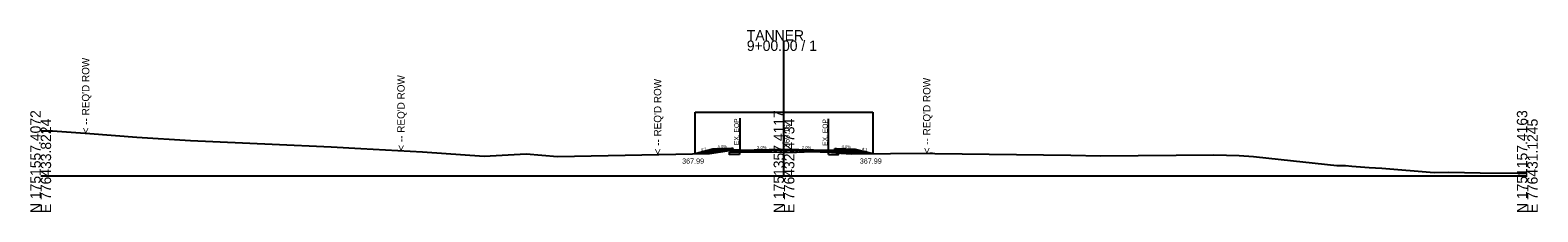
# Model space of a CAD drawing. Extents: x 774192 to 776597, y 1750236 to 1752784.
# Drawn here: x 774680.5 to 775086.2, y 1751748.9 to 1751797.8 of the extents above; entities that cross this region are included whole.
import ezdxf

# ---------------------------------------------------------------- set-up
doc = ezdxf.new("R2010")
doc.units = 0
for name, color, linetype in [('ControlPoints', 7, 'Continuous'), ('Default', 7, 'Continuous'), ('Observations', 7, 'Continuous'), ('Setups', 7, 'Continuous'), ('SHEET_BORDER_TX', 7, 'Continuous'), ('SHEET_DATE_DGN_TX', 7, 'Continuous'), ('SHEET_LOGO', 7, 'Continuous'), ('SHEET_PLOTTING_SHAPE', 7, 'Continuous'), ('SHEET_PRELIM', 7, 'Continuous'), ('SHEET_PROJ_NUMBER', 7, 'Continuous'), ('SHEET_TITLE_BLOCK_TX', 7, 'Continuous'), ('SHEET_WORK_NUMBER', 7, 'Continuous'), ('TS_BACKBONE', 7, 'Continuous'), ('TS_DIMENSIONS', 7, 'Continuous')]:
    doc.layers.add(name, color=color, linetype=linetype)

msp = doc.modelspace()

# ---------------------------------------------------------------- linework, layer by layer
at = {"layer": 'ControlPoints'}
msp.add_lwpolyline([(774683.33, 1751770.73), (774686.53, 1751770.71), (774696.56, 1751769.97), (774709.16, 1751768.98), (774723.68, 1751768.1), (774745.63, 1751767.12), (774761.49, 1751766.44), (774769.51, 1751765.91), (774786.05, 1751765.06), (774802.69, 1751763.89), (774813.95, 1751764.55), (774822.43, 1751763.79), (774863.28, 1751764.64), (774869.17, 1751765.48), (774869.52, 1751765.18), (774869.9, 1751765.28), (774871.42, 1751765.09), (774883.33, 1751764.99), (774886.74, 1751765), (774890.92, 1751765.1), (774895.22, 1751764.93), (774897.31, 1751764.76), (774901.44, 1751764.53), (774922.53, 1751764.66), (774923.32, 1751764.65), (774923.93, 1751764.64), (774960.53, 1751764.12), (774968.46, 1751764.01), (774998.95, 1751764.23), (775005.77, 1751764.07), (775009.7, 1751763.79), (775013.78, 1751763.39), (775032.11, 1751761.37), (775034.43, 1751761.33), (775036.09, 1751761.17), (775040.8, 1751760.86), (775044.2, 1751760.64), (775058.32, 1751759.48), (775062.18, 1751759.57), (775070.68, 1751759.42), (775080.8, 1751759.34), (775083.33, 1751759.3)], dxfattribs=at)
at = {"layer": 'Default'}
for p, q in [((774871.34, 1751765.33), (774883.34, 1751765.57)), ((774883.33, 1751765.57), (774895.33, 1751765.33))]:
    msp.add_line(p, q, dxfattribs=at)
at = {"layer": 'Setups'}
for p, q in [((774883.33, 1751758.57), (774883.33, 1751795.04)), ((774683.33, 1751758.57), (774883.33, 1751758.57)), ((774883.33, 1751758.57), (775083.33, 1751758.57))]:
    msp.add_line(p, q, dxfattribs=at)
at = {"layer": 'SHEET_BORDER_TX'}
for p, q in [((774868.67, 1751764.27), (774868.67, 1751764.94)), ((774871.35, 1751764.33), (774868.67, 1751764.27)), ((774895.32, 1751764.33), (774898, 1751764.27)), ((774898, 1751764.27), (774898, 1751764.94))]:
    msp.add_line(p, q, dxfattribs=at)
for points in [[(774868.67, 1751764.94), (774871.33, 1751764.99), (774871.35, 1751764.33)], [(774895.32, 1751764.33), (774895.33, 1751764.99), (774898, 1751764.94)]]:
    msp.add_lwpolyline(points, dxfattribs=at)
at = {"layer": 'SHEET_LOGO'}
for p, q in [((774871.42, 1751774.09), (774871.42, 1751765.09)), ((774895.22, 1751773.93), (774895.22, 1751764.93))]:
    msp.add_line(p, q, dxfattribs=at)
at = {"layer": 'SHEET_PLOTTING_SHAPE'}
for p, q in [((774869.17, 1751764.95), (774869.17, 1751765.95)), ((774871.33, 1751765.49), (774871.33, 1751764.99)), ((774895.33, 1751765.49), (774895.33, 1751764.99)), ((774897.5, 1751764.95), (774897.5, 1751765.95)), ((774871.33, 1751764.99), (774869.17, 1751764.95)), ((774895.33, 1751764.99), (774897.5, 1751764.95))]:
    msp.add_line(p, q, dxfattribs=at)
at = {"layer": 'SHEET_PROJ_NUMBER'}
for p, q in [((774859.42, 1751764.56), (774859.42, 1751775.73)), ((774859.42, 1751775.73), (774907.23, 1751775.73)), ((774907.23, 1751775.73), (774907.23, 1751764.57))]:
    msp.add_line(p, q, dxfattribs=at)
at = {"layer": 'SHEET_TITLE_BLOCK_TX'}
for p, q in [((774864.17, 1751765.75), (774859.42, 1751764.56)), ((774869.17, 1751765.95), (774864.17, 1751765.75)), ((774869.67, 1751765.96), (774869.17, 1751765.95)), ((774869.67, 1751765.46), (774869.67, 1751765.96)), ((774871.33, 1751765.49), (774869.67, 1751765.46)), ((774871.33, 1751765.49), (774883.33, 1751765.73)), ((774883.33, 1751765.73), (774895.33, 1751765.49)), ((774895.33, 1751765.49), (774897, 1751765.46)), ((774897, 1751765.46), (774897, 1751765.96)), ((774897, 1751765.96), (774897.5, 1751765.95)), ((774897.5, 1751765.95), (774902.5, 1751765.75)), ((774902.5, 1751765.75), (774907.23, 1751764.57))]:
    msp.add_line(p, q, dxfattribs=at)
at = {"layer": 'SHEET_WORK_NUMBER'}
msp.add_line((774895.33, 1751764.99), (774895.33, 1751764.92), dxfattribs=at)
for points in [[(774871.33, 1751765.11), (774871.42, 1751765.09), (774874.94, 1751765.06)], [(774874.94, 1751765.06), (774883.33, 1751764.99), (774886.74, 1751765), (774890.92, 1751765.1), (774895.22, 1751764.93), (774895.33, 1751764.92)]]:
    msp.add_lwpolyline(points, dxfattribs=at)
at = {"layer": 'TS_BACKBONE'}
for p, q in [((774861.67, 1751765.13), (774861.67, 1751764.95)), ((774862.07, 1751765.23), (774862.07, 1751764.95)), ((774863, 1751765.46), (774863.17, 1751765.46)), ((774863.27, 1751765.53), (774863.27, 1751764.95)), ((774863.67, 1751765.63), (774863.67, 1751764.95)), ((774864.07, 1751765.73), (774864.07, 1751764.95)), ((774864.17, 1751765.46), (774865.17, 1751765.46)), ((774865.27, 1751765.79), (774865.27, 1751764.95)), ((774865.67, 1751765.81), (774865.67, 1751764.98)), ((774866.07, 1751765.83), (774866.07, 1751765.04)), ((774866.17, 1751765.46), (774867.17, 1751765.46)), ((774866.84, 1751765.86), (774867.17, 1751765.86)), ((774867.27, 1751765.87), (774867.27, 1751765.21)), ((774867.67, 1751765.89), (774867.67, 1751765.27)), ((774868.07, 1751765.91), (774868.07, 1751765.32)), ((774868.17, 1751765.86), (774869.17, 1751765.86)), ((774868.17, 1751765.46), (774869, 1751765.46)), ((774869.27, 1751765.95), (774869.27, 1751764.95)), ((774869.67, 1751765.46), (774869.67, 1751764.96)), ((774870.07, 1751765.47), (774870.07, 1751764.97)), ((774870.17, 1751765.46), (774871.17, 1751765.46)), ((774871.27, 1751765.49), (774871.27, 1751764.99)), ((774871.33, 1751765.48), (774871.35, 1751765.49)), ((774871.33, 1751765.13), (774871.47, 1751764.99)), ((774872.28, 1751765.01), (774872.79, 1751765.52)), ((774872.36, 1751765.51), (774872.85, 1751765.02)), ((774873.73, 1751765.04), (774874.24, 1751765.55)), ((774873.75, 1751765.54), (774874.24, 1751765.05)), ((774875.14, 1751765.57), (774875.65, 1751765.06)), ((774875.16, 1751765.06), (774875.68, 1751765.58)), ((774876.52, 1751765.6), (774877.07, 1751765.05)), ((774876.56, 1751765.05), (774877.12, 1751765.61)), ((774877.91, 1751765.62), (774878.5, 1751765.03)), ((774877.97, 1751765.04), (774878.56, 1751765.64)), ((774879.3, 1751765.65), (774879.93, 1751765.02)), ((774879.37, 1751765.03), (774880.01, 1751765.67)), ((774880.68, 1751765.68), (774881.35, 1751765.01)), ((774880.77, 1751765.01), (774881.45, 1751765.69)), ((774882.07, 1751765.71), (774882.78, 1751765)), ((774882.17, 1751765), (774882.89, 1751765.72)), ((774883.46, 1751765.73), (774884.2, 1751764.99)), ((774883.58, 1751764.99), (774884.3, 1751765.71)), ((774884.9, 1751765.7), (774885.61, 1751765)), ((774885, 1751765), (774885.68, 1751765.69)), ((774886.35, 1751765.67), (774887.01, 1751765.01)), ((774886.41, 1751765), (774887.07, 1751765.66)), ((774887.79, 1751765.64), (774888.39, 1751765.04)), ((774887.85, 1751765.03), (774888.46, 1751765.63)), ((774889.23, 1751765.61), (774889.77, 1751765.07)), ((774889.3, 1751765.06), (774889.84, 1751765.6)), ((774890.68, 1751765.59), (774891.17, 1751765.09)), ((774890.75, 1751765.1), (774891.23, 1751765.57)), ((774892.12, 1751765.56), (774892.64, 1751765.03)), ((774892.12, 1751765.05), (774892.62, 1751765.55)), ((774893.48, 1751765), (774894, 1751765.52)), ((774893.56, 1751765.53), (774894.12, 1751764.97)), ((774894.84, 1751764.94), (774895.33, 1751765.44)), ((774895, 1751765.5), (774895.33, 1751765.17)), ((774895.33, 1751765.46), (774895.5, 1751765.46)), ((774895.61, 1751765.49), (774895.61, 1751764.99)), ((774896.01, 1751765.48), (774896.01, 1751764.98)), ((774896.41, 1751765.47), (774896.41, 1751764.97)), ((774896.5, 1751765.46), (774897.5, 1751765.46)), ((774897, 1751765.96), (774897, 1751765.95)), ((774897, 1751765.86), (774897.5, 1751765.86)), ((774897.4, 1751765.95), (774897.4, 1751765.95)), ((774897.61, 1751765.94), (774897.61, 1751764.95)), ((774898.01, 1751765.93), (774898.01, 1751764.95)), ((774898.41, 1751765.91), (774898.41, 1751764.95)), ((774898.5, 1751765.86), (774899.5, 1751765.86)), ((774898.5, 1751765.46), (774899.5, 1751765.46)), ((774899.61, 1751765.86), (774899.61, 1751764.95)), ((774900.01, 1751765.85), (774900.01, 1751764.95)), ((774900.41, 1751765.83), (774900.41, 1751764.95)), ((774900.5, 1751765.46), (774901.5, 1751765.46)), ((774901.61, 1751765.78), (774901.61, 1751764.95)), ((774902.01, 1751765.77), (774902.01, 1751764.95)), ((774902.41, 1751765.75), (774902.41, 1751764.95)), ((774902.5, 1751765.46), (774903.5, 1751765.46)), ((774903.61, 1751765.47), (774903.61, 1751764.95)), ((774904.01, 1751765.37), (774904.01, 1751764.95)), ((774904.41, 1751765.27), (774904.41, 1751764.95)), ((774860.27, 1751764.77), (774860.27, 1751764.58)), ((774860.67, 1751764.87), (774860.67, 1751764.59)), ((774861.07, 1751764.96), (774861.07, 1751764.6)), ((774861.17, 1751764.86), (774862.17, 1751764.86)), ((774861.27, 1751765.03), (774861.27, 1751764.95)), ((774862.17, 1751765.06), (774863.17, 1751765.06)), ((774862.27, 1751764.96), (774862.27, 1751764.62)), ((774862.67, 1751764.96), (774862.67, 1751764.63)), ((774863.07, 1751764.96), (774863.07, 1751764.64)), ((774863.17, 1751764.86), (774864.17, 1751764.86)), ((774864.17, 1751765.06), (774865.17, 1751765.06)), ((774864.27, 1751764.96), (774864.27, 1751764.78)), ((774864.67, 1751764.96), (774864.67, 1751764.84)), ((774865.07, 1751764.96), (774865.07, 1751764.9)), ((774866.17, 1751765.06), (774866.19, 1751765.06)), ((774870.17, 1751765.06), (774871.17, 1751765.06)), ((774895.33, 1751765.06), (774895.5, 1751765.06)), ((774895.4, 1751764.96), (774895.4, 1751764.92)), ((774895.61, 1751764.99), (774895.61, 1751764.95)), ((774896.01, 1751764.98), (774896.01, 1751764.95)), ((774896.11, 1751764.86), (774896.5, 1751764.86)), ((774896.41, 1751764.97), (774896.41, 1751764.95)), ((774896.5, 1751765.06), (774897.5, 1751765.06)), ((774896.6, 1751764.96), (774896.6, 1751764.81)), ((774897, 1751764.96), (774897, 1751764.78)), ((774897.4, 1751764.96), (774897.4, 1751764.95)), ((774897.4, 1751764.95), (774897.4, 1751764.75)), ((774897.5, 1751764.86), (774898.5, 1751764.86)), ((774898.5, 1751765.06), (774899.5, 1751765.06)), ((774898.6, 1751764.96), (774898.6, 1751764.69)), ((774899, 1751764.96), (774899, 1751764.66)), ((774899.4, 1751764.96), (774899.4, 1751764.64)), ((774899.5, 1751764.86), (774900.5, 1751764.86)), ((774900.5, 1751765.06), (774901.5, 1751765.06)), ((774900.6, 1751764.96), (774900.6, 1751764.58)), ((774901, 1751764.96), (774901, 1751764.56)), ((774901.4, 1751764.96), (774901.4, 1751764.53)), ((774901.5, 1751764.86), (774902.5, 1751764.86)), ((774902.5, 1751765.06), (774903.5, 1751765.06)), ((774902.6, 1751764.96), (774902.6, 1751764.54)), ((774903, 1751764.96), (774903, 1751764.54)), ((774903.4, 1751764.96), (774903.4, 1751764.54)), ((774903.5, 1751764.86), (774904.5, 1751764.86)), ((774904.5, 1751765.06), (774905.27, 1751765.06)), ((774904.6, 1751764.96), (774904.6, 1751764.55)), ((774905, 1751764.96), (774905, 1751764.55)), ((774905.4, 1751764.96), (774905.4, 1751764.56)), ((774905.5, 1751764.86), (774906.07, 1751764.86)), ((774905.61, 1751764.97), (774905.61, 1751764.95)), ((774906.6, 1751764.72), (774906.6, 1751764.56)), ((774907, 1751764.62), (774907, 1751764.57))]:
    msp.add_line(p, q, dxfattribs=at)

# ---------------------------------------------------------------- texts
at = {"layer": 'Observations'}
for p in [(774855.92, 1751761.86), (774903.73, 1751761.87)]:
    msp.add_text('367.99', height=1.4, dxfattribs=at).set_placement(p)
at = {"layer": 'Setups'}
for s, p in [('TANNER', (774873.33, 1751795.04)), ('9+00.00 / 1', (774873.33, 1751792.24))]:
    msp.add_text(s, height=2.8, dxfattribs=at).set_placement(p)
for s, p in [('N 1751557.4072', (774683.33, 1751748.57)), ('E 776433.8224', (774686.13, 1751748.57)), ('N 1751357.4117', (774883.33, 1751748.57)), ('E 776432.4734', (774886.13, 1751748.57)), ('N 1751157.4163', (775083.33, 1751748.57)), ('E 776431.1245', (775086.13, 1751748.57))]:
    msp.add_text(s, height=2.8, rotation=90, dxfattribs=at).set_placement(p)
at = {"layer": 'SHEET_DATE_DGN_TX'}
for s, rotation, p in [('4:1', 14.0362, (774861.08, 1751765.18)), ('4.0%', 2.2906, (774865.44, 1751766)), ('2.0%', 1.1458, (774876.11, 1751765.79)), ('2.0%', 358.8542, (774888.11, 1751765.84)), ('4.0%', 357.7094, (774898.79, 1751766.1)), ('4:1', 345.9638, (774904.25, 1751765.52))]:
    msp.add_text(s, height=0.8, rotation=rotation, dxfattribs=at).set_placement(p)
at = {"layer": 'SHEET_LOGO'}
for p in [(774871.22, 1751766.86), (774895.02, 1751766.69)]:
    msp.add_text('EX. EOP', height=1.3, rotation=90, dxfattribs=at).set_placement(p)
at = {"layer": 'SHEET_PRELIM'}
msp.add_text(' 369.16', height=1.5, rotation=90, dxfattribs=at).set_placement((774884.83, 1751765.73))
at = {"layer": 'TS_DIMENSIONS'}
for p in [(774696.42, 1751770.05), (774781.27, 1751765.36), (774850.32, 1751764.35), (774922.75, 1751764.65)]:
    msp.add_text("< -- REQ'D ROW", height=2, rotation=90, dxfattribs=at).set_placement(p)

doc.saveas('drawing.dxf')
